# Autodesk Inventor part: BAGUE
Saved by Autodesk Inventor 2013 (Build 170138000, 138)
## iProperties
Created: 2012-12
Part Number: BAGUE
Material: Générique
Document SubType Name: Modeling
Designer: jost thierry
Density: 1 g/cm^3
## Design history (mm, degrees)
node "BAGUE1"
node "BAGUE"
node "Base1"
